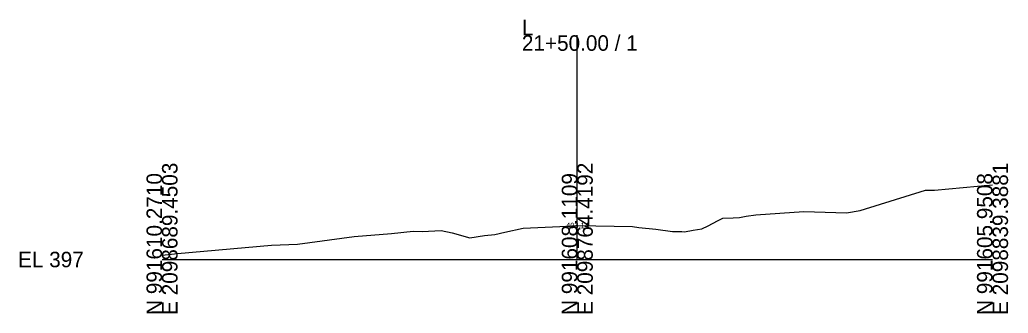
# Model space of a CAD drawing. Extents: x -26 to 3453, y -10 to 9553.
# Drawn here: x 974.3 to 1152.8, y -9.7 to 43.3 of the extents above; entities that cross this region are included whole.
import ezdxf

# ---------------------------------------------------------------- set-up
doc = ezdxf.new("R2010")
doc.units = 0
for name, color, linetype in [('Default', 7, 'Continuous'), ('Exist Cross Section Cell', 7, 'Continuous'), ('Exist XS Center Line Elevation Label', 7, 'Continuous'), ('Exist XS Ground Line', 7, 'Continuous')]:
    doc.layers.add(name, color=color, linetype=linetype)

msp = doc.modelspace()

# ---------------------------------------------------------------- linework, layer by layer
at = {"layer": 'Exist Cross Section Cell'}
for p, q in [((1075, 0), (1075, 40.48)), ((1000, 0), (1075, 0)), ((1075, 0), (1150, 0))]:
    msp.add_line(p, q, dxfattribs=at)
at = {"layer": 'Exist XS Ground Line'}
msp.add_lwpolyline([(1000, 0.77), (1002.82, 1.08), (1019.79, 2.59), (1024.48, 2.78), (1034.72, 4.13), (1041.47, 4.71), (1045.35, 5.09), (1046.99, 5.06), (1050.43, 5.22), (1052.41, 4.8), (1055.58, 3.92), (1058.25, 4.35), (1060.1, 4.54), (1061.93, 4.93), (1065.22, 5.65), (1071.86, 5.98), (1075.08, 6.14), (1078.34, 6.08), (1085, 5.96), (1086.11, 5.81), (1089.2, 5.46), (1092.22, 5.08), (1092.89, 5.06), (1093.91, 5.08), (1094.38, 5.01), (1095.92, 5.3), (1097.52, 5.53), (1098.66, 6.1), (1100.3, 6.98), (1101.32, 7.48), (1103.17, 7.52), (1104.31, 7.6), (1105.51, 7.8), (1107.23, 8.08), (1115.92, 8.67), (1123.63, 8.4), (1126.11, 8.84), (1137.87, 12.53), (1138.62, 12.55), (1139.53, 12.53), (1147.28, 13.22), (1147.99, 13.29), (1148.47, 13.34), (1148.9, 13.39), (1150, 13.49)], dxfattribs=at)

# ---------------------------------------------------------------- texts
at = {"layer": 'Default'}
msp.add_text('-', height=0.0001, dxfattribs=at).set_placement((1000, 0))
at = {"layer": 'Exist Cross Section Cell'}
for s, p in [('L', (1065, 40.48)), ('21+50.00 / 1', (1065, 37.68)), ('EL 397', (974, -1.4))]:
    msp.add_text(s, height=2.8, dxfattribs=at).set_placement(p)
for s, p in [('E 2098689.4503', (1002.8, -10)), ('E 2098764.4192', (1077.8, -10)), ('E 2098839.3881', (1152.8, -10)), ('N 991610.2710', (1000, -10)), ('N 991608.1109', (1075, -10)), ('N 991605.9508', (1150, -10))]:
    msp.add_text(s, height=2.8, rotation=90, dxfattribs=at).set_placement(p)
at = {"layer": 'Exist XS Center Line Elevation Label'}
msp.add_text('403.14', height=1, dxfattribs=at).set_placement((1072.98, 5.64))

doc.saveas('drawing.dxf')
